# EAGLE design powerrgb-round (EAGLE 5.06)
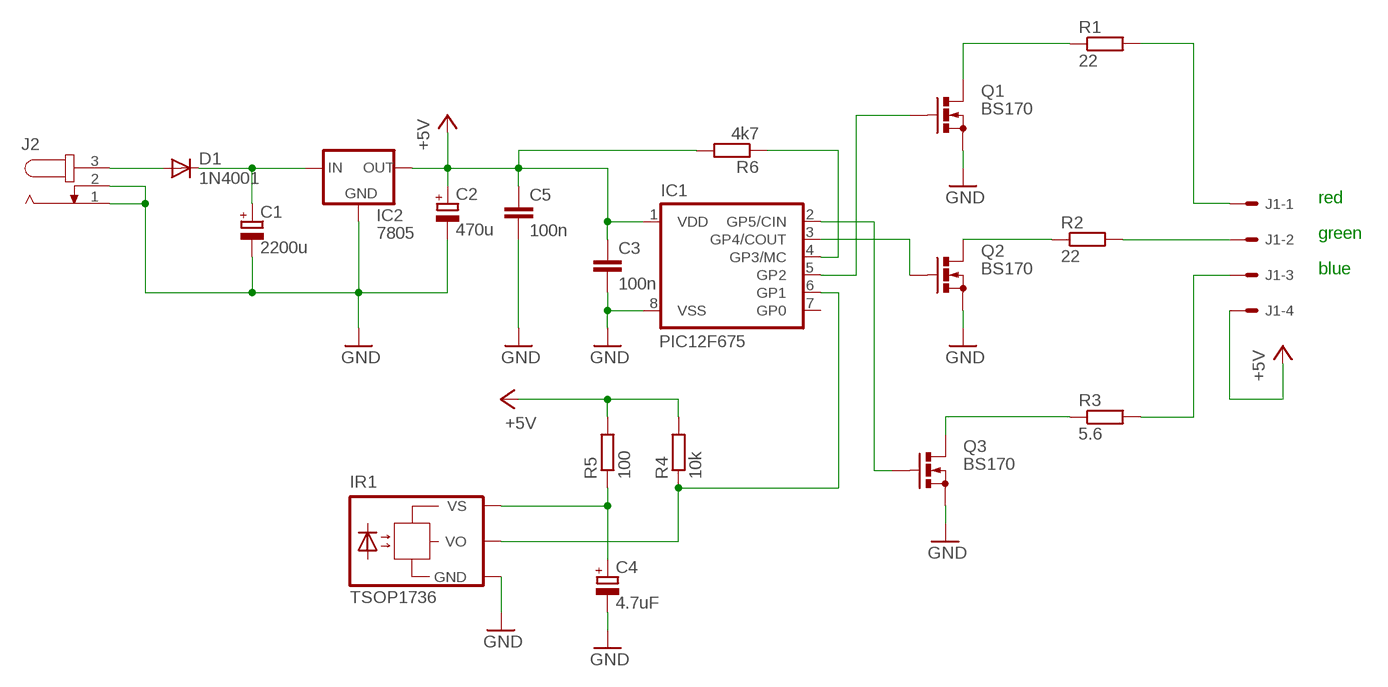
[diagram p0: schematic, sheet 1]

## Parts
C1  2200u  CPOL-EUE7.5-16  [E7,5-16]
C2  470u  CPOL-EUE5-10.5  [E5-10,5]
C3  100n  C-EU050-025X075  [C050-025X075]
C4  4.7uF  CPOL-EUE2,5-6E  [E2,5-6E]
C5  100n  C-EU050-025X075  [C050-025X075]
D1  1N4001  1N4004  [DO41-10]
IC1  PIC12F675  PIC12C672P  [DIL8]
IC2  7805  78XXS  [78XXS]
IR1  TSOP1736  TSOP17TB1VERTICAL  [TSOP17_TB1_VERTICAL]
J1  22-05-7048-04  [7395-04]
J2  JACK-PLUG0  [SPC4077]
Q1  BS170  [SOT54E]
Q2  BS170  [SOT54E]
Q3  BS170  [SOT54E]
R1  22  R-EU_0411/15  [0411/15]
R2  22  R-EU_0411/15  [0411/15]
R3  5.6  R-EU_0411/15  [0411/15]
R4  10k  R-EU_0207/10  [0207/10]
R5  100  R-EU_0207/10  [0207/10]
R6  4k7  R-EU_0207/10  [0207/10]

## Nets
+5V: C2.+ C3.1 C5.1 IC1.1(VDD) IC2.OUT J1.4 R4.2 R5.2 R6.2
GND: C1.- C2.- C3.2 C4.- C5.2 IC1.8(VSS) IC2.GND IR1.GND J2.1 J2.2 Q1.S Q2.S Q3.S
N$1: C1.+ D1.C IC2.IN
N$2: IC1.4(GP3/MC) R6.1
N$5: C4.+ IR1.VS R5.1
N$6: Q3.D R3.1
N$7: Q2.D R2.1
N$8: Q1.D R1.1
N$9: J1.3 R3.2
N$10: J1.2 R2.2
N$11: J1.1 R1.2
N$12: IC1.2(GP5/CIN) Q3.G
N$13: IC1.5(GP2) Q1.G
N$14: IC1.3(GP4/COUT) Q2.G
N$15: IC1.6(GP1) IR1.VO R4.1
N$17: D1.A J2.3
Unconnected: IC1.7(GP0)

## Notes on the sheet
- red
- green
- blue

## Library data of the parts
C1 C2 C4 = rcl:CPOL-EU: POLARIZED CAPACITOR, European symbol
C3 C5 = rcl:C-EU: CAPACITOR, European symbol
D1 = diode:1N4004: DIODE
IC1 = microchip:PIC12C*?: MICROCONTROLLER
IC2 = v-reg:78XXS: VOLTAGE REGULATOR
IR1 = pic-rgb-lib:TSOP17*TB1: TSOP17..TB1 IR Receiver Modules for Remote Control Systems Source: http://www.vishay.com/docs/82042/82042.pdf
J1 = con-molex:22-?-04: CONNECTOR wire to board 2.54 mm (.1 inch) pitch header
J2 = con-jack:JACK-PLUG: DC POWER JACK Power Jack, DC, Right Angle, Through Hole, Rated 5A at 16VDC, PC Terminals Distributor: Farnell (www.Farnell.de) Drawing: 84N1161.pdf / 84N1162.pdf Manufacturer: SPC Technology (www.spctechnology.com) Type: SPC4077 / SPC 4078
Q1-Q3 = transistor-small-signal:BS170: N-CHANNEL MOS FET
R1-R6 = rcl:R-EU_: RESISTOR, European symbol

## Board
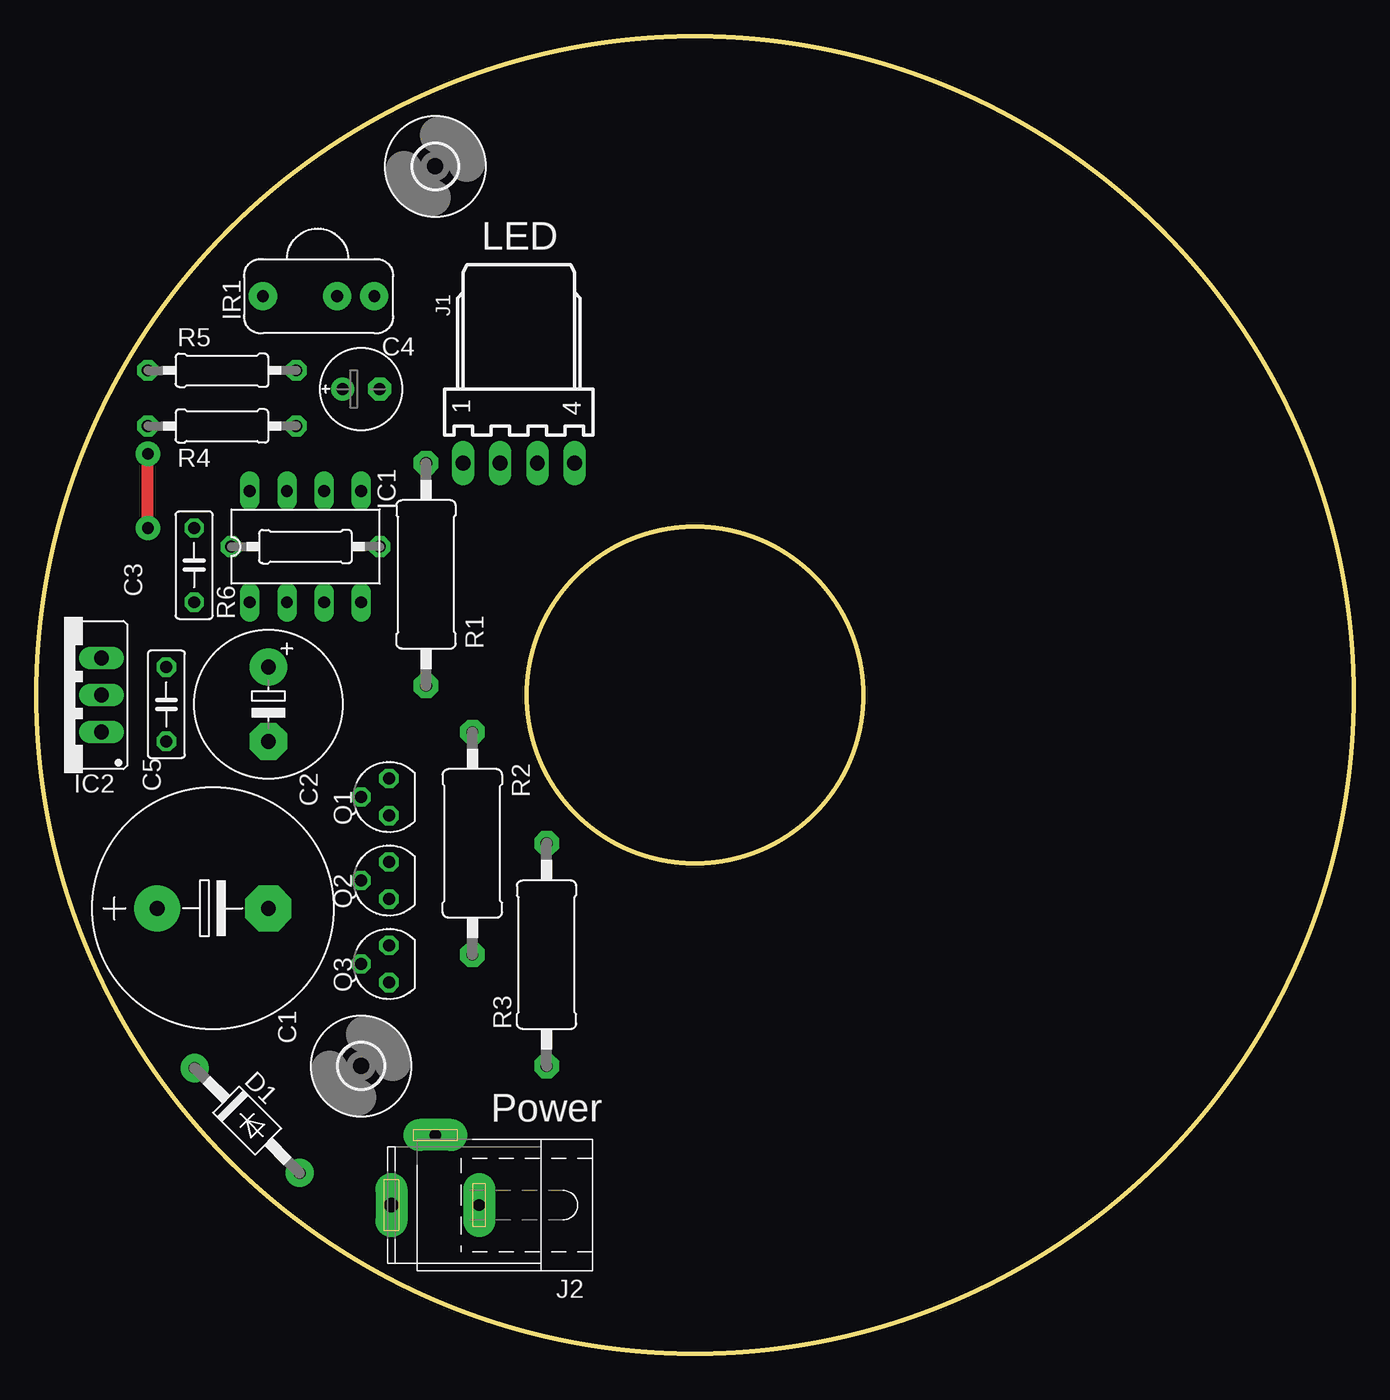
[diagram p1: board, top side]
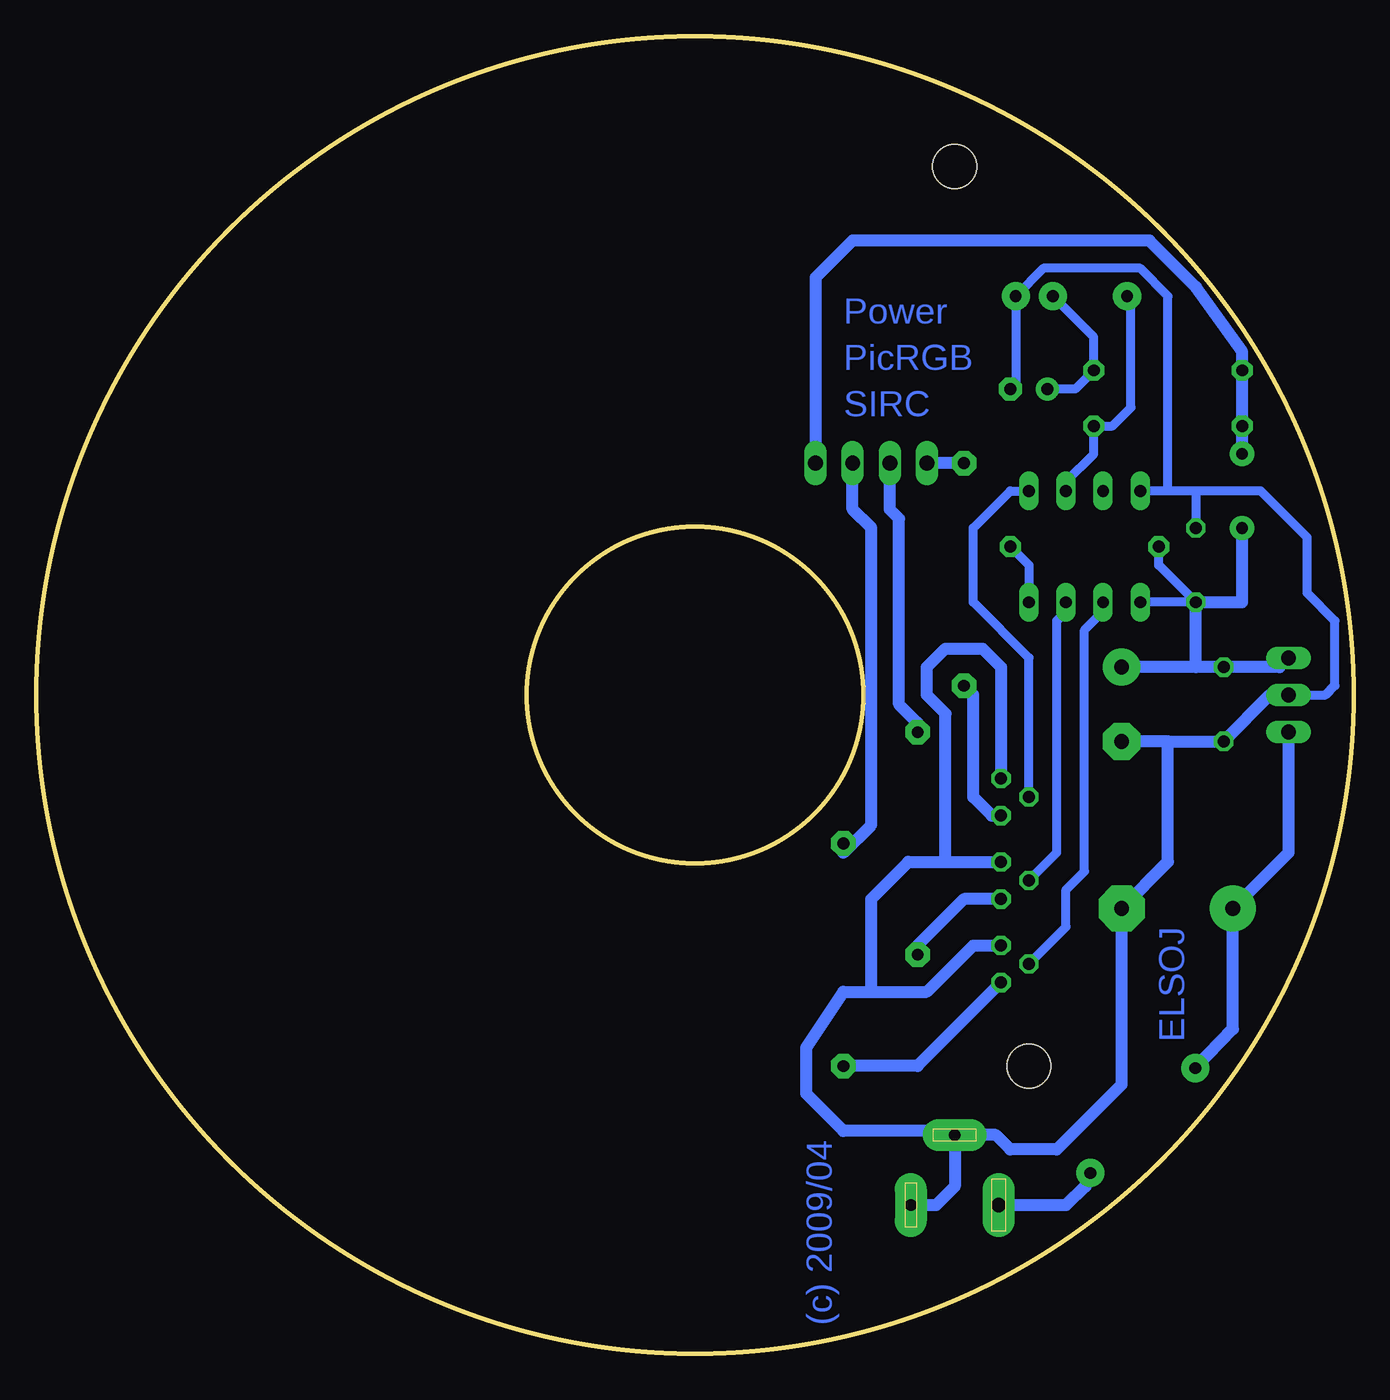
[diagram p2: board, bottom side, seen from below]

Size 90.17 x 90.17 mm. Coordinates in mm from the lower left corner, seen from the top.
Outline: circle at 45.09,45.09 radius 45.09
Outline: circle at 45.09,45.09 radius 11.5
Copper layers (1*16): Top 0.035mm / dielectric 1.5mm / Bottom 0.035mm
Design rules "default": minimum track width 10mil, minimum drill 24mil, track to track 8mil, track to pad 8mil, pad to pad 8mil, via to via 8mil, smd to smd 8mil, copper to edge 40mil, drill to drill 8mil, minimum pad ring 10mil, minimum via ring 8mil, stop-mask expansion 4mil, vias tented up to drill 0mil, thermal gap 10mil

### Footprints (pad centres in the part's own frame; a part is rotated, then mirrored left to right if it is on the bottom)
E7,5-16 = drill 1.016 pad 3.15 round: + -3.81,0 | drill 1.016 pad 3.15 octagon: - 3.81,0
E5-10,5 = drill 1.016 pad 2.54 round: + -2.54,0 | drill 1.016 pad 2.54 octagon: - 2.54,0
C050-025X075 = drill 0.813 octagon: 1 -2.54,0; 2 2.54,0
E2,5-6E = drill 0.813 pad 1.575 round: + -1.27,0 | drill 0.813 pad 1.575 octagon: - 1.27,0
DO41-10 = drill 0.8 pad 1.93 round: A 5.08,0; C -5.08,0
DIL8 = drill 0.813 long: 1 -3.81,-3.81; 2 -1.27,-3.81; 3 1.27,-3.81; 4 3.81,-3.81; 5 3.81,3.81; 6 1.27,3.81; 7 -1.27,3.81; 8 -3.81,3.81
78XXS = drill 1.016 long: GND 0,-2.54; IN -2.54,-2.54; OUT 2.54,-2.54
TSOP17_TB1_VERTICAL = drill 0.8 pad 1.93 round: GND 3.81,0; VO -3.81,0; VS 1.27,0
7395-04 = drill 1.016 long: 1 3.81,0; 2 1.27,0; 3 -1.27,0; 4 -3.81,0
SPC4077 = drill 0.8 pad 2.184 long: 1 -3,0; 2 0,-4.8 | drill 1 pad 2.184 long: 3 3,0
SOT54E = drill 0.813 octagon: D -1.27,0; G 0,1.905; S 1.27,0
0411/15 = drill 0.8 pad 1.676 octagon: 1 -7.62,0; 2 7.62,0
0207/10 = drill 0.813 pad 1.422 octagon: 1 -5.08,0; 2 5.08,0
3,0 = hole 3: 0,0

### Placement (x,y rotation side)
C1  12.06,30.48 0 top
C2  15.88,44.45 270 top
C3  10.79,53.98 90 top
C4  22.23,66.04 0 top
C5  8.89,44.45 270 top
D1  14.42,15.95 315 top
IC1  18.41,55.24 0 top
IC2  1.91,45.09 90 top
IR1  19.31,72.39 0 top
J1  33.02,60.96 180 top
J2  27.3,10.16 180 top
Q1  24.13,38.1 90 top
Q2  24.13,32.38 90 top
Q3  24.13,26.67 90 top
R1  26.67,53.34 90 top
R2  29.84,34.92 90 top
R3  34.92,27.3 90 top
R4  12.7,63.5 180 top
R5  12.7,67.31 180 top
R6  18.41,55.24 180 top
U$1  [3,0]  22.23,19.68 0 top
U$2  [3,0]  27.3,81.28 0 top

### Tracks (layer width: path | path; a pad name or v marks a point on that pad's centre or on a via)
+5V  (via drill 0.8 pad 1.68)
  Top 0.813: v7.62,56.52 v7.62,61.59
  Bottom 0.61: IC1.1 C3.1 13.34,53.98 R6.2
  Bottom 0.813: v7.62,61.59 R4.2 R5.2 7.62,68.58 10.79,73.03 13.97,76.2 34.29,76.2 36.83,73.66 J1.4 | v7.62,56.52 7.62,51.44 C3.1 10.79,46.99 | 10.79,46.99 C5.1 5.08,46.99 IC2.OUT | 10.79,46.99 C2.+
GND
  Bottom 0.61: 10.79,59.05 6.35,59.05 3.17,55.88 3.17,52.07 1.27,50.16 1.27,45.72 1.91,45.09 IC2.GND | 10.79,59.05 C3.2 | C4.- 23.12,66.41 IR1.GND 21.22,74.3 14.61,74.3 12.7,72.39 12.7,59.05 | 10.79,59.05 12.7,59.05 | J2.2 27.59,15.24 | 12.7,59.05 IC1.8
  Bottom 0.813: Q3.S 26.04,27.94 29.21,24.77 33.02,24.77 | 27.94,33.66 30.48,33.66 33.02,31.11 33.02,24.77 | 27.94,33.66 Q2.S | 27.94,33.66 27.94,43.81 29.21,45.09 29.21,46.99 27.94,48.26 25.4,48.26 24.13,46.99 Q1.S | IC2.GND 5.71,45.09 C5.2 12.7,41.91 | 12.7,41.91 12.7,33.66 C1.- 15.88,18.41 20.32,13.97 23.5,13.97 24.48,14.96 J2.2 27.3,11.43 28.57,10.16 J2.1 | 12.7,41.91 C2.- | 33.02,24.77 34.92,24.77 37.47,20.95 37.47,17.78 34.92,15.24 27.59,15.24
N$1
  Bottom 0.813: D1.C 8.26,22.23 C1.+ 4.45,34.29 IC2.IN
N$2
  Bottom 0.61: R6.1 22.23,53.98 IC1.4
N$5
  Bottom 0.61: C4.+ 19.05,66.04 R5.1 17.78,69.59 IR1.VS
N$6
  Bottom 0.813: Q3.D 29.84,19.68 R3.1
N$7
  Bottom 0.813: R2.1 29.84,27.94 26.67,31.11 Q2.D
N$8
  Bottom 0.813: Q1.D 24.77,36.83 26.04,38.1 26.04,45.09 R1.1
N$9
  Bottom 0.813: R3.2 34.92,34.29 33.02,36.2 33.02,56.52 34.29,57.78 J1.3
N$10
  Bottom 0.813: R2.2 29.84,43.18 31.11,44.45 31.11,57.15 31.75,57.78 J1.2
N$11
  Bottom 0.813: R1.2 J1.1
N$12
  Bottom 0.61: IC1.2 17.14,50.8 18.41,49.53 18.41,33.02 19.68,31.75 19.68,29.21 Q3.G
N$13
  Bottom 0.61: IC1.5 23.5,59.05 26.04,56.52 26.04,51.44 22.23,47.62 Q1.G
N$14
  Bottom 0.61: IC1.3 19.68,50.8 20.32,50.16 20.32,34.29 Q2.G
N$15
  Bottom 0.61: IC1.6 19.68,59.69 17.78,61.59 R4.1 16.51,63.5 15.24,64.77 15.24,72.13 IR1.VO
N$17
  Bottom 0.813: D1.A 18.35,11.43 19.68,10.16 J2.3

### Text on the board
Bottom: Power | PicRGB | SIRC | ELSOJ | (c) 2009/04
tPlace: LED | Power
